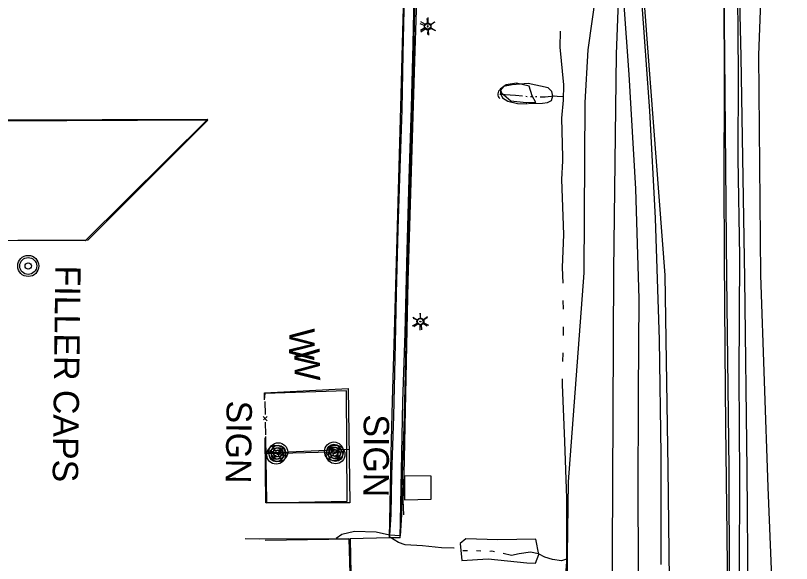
# Model space of a CAD drawing. Extents: x 588843 to 2552415, y 180129 to 269402.
# Drawn here: x 593696.8 to 593880.6, y 185185.1 to 185314.8 of the extents above; entities that cross this region are included whole.
import ezdxf

# ---------------------------------------------------------------- set-up
doc = ezdxf.new("R2010")
doc.units = 0
for name, color, linetype in [('Default', 7, 'Continuous'), ('E_BLD', 7, 'Continuous'), ('E_BLD_HvyDash', 7, 'Continuous'), ('E_DRN', 7, 'Continuous'), ('E_DRN_RipRap', 7, 'Continuous'), ('E_DWY', 7, 'Continuous'), ('E_FEN_P', 7, 'Continuous'), ('E_LTG', 7, 'Continuous'), ('E_MISCPROP', 7, 'Continuous'), ('E_MISCPROP_Text', 7, 'Continuous'), ('E_RDWY', 7, 'Continuous'), ('E_RDWY_AsphConc', 7, 'Continuous'), ('E_RDWY_C_and_G', 7, 'Continuous'), ('E_RDWY_Gravel', 7, 'Continuous'), ('E_RDWY_PavtEdge', 7, 'Continuous'), ('E_SGN', 7, 'Continuous'), ('E_SGN_Text', 7, 'Continuous'), ('E_WAL', 7, 'Continuous'), ('E_WAL_Text', 7, 'Continuous'), ('E_WTR_P', 7, 'Continuous')]:
    doc.layers.add(name, color=color, linetype=linetype)

# ---------------------------------------------------------------- blocks, each defined once
blk = doc.blocks.new('FILO')
at = {"layer": 'E_MISCPROP'}
for radius in [5, 4, 1.5]:
    blk.add_circle((0, 0), radius, dxfattribs=at)
blk = doc.blocks.new('FILT')
at = {"layer": 'E_MISCPROP_Text'}
blk.add_text('FILLER CAPS', height=12, dxfattribs=at).set_placement((12, -4))
blk = doc.blocks.new('POLE')
at = {"layer": 'Default'}
for radius in [4.46, 3.35, 2.23, 1.12]:
    blk.add_circle((0, 0), radius, dxfattribs=at)
blk = doc.blocks.new('SIGN')
at = {"layer": 'Default'}
blk.add_text('SIGN', height=12, dxfattribs=at).set_placement((-18.55, -6))
blk = doc.blocks.new('LPOL')
at = {"layer": 'Default'}
for p, q in [((-4, 0), (-1.5, 0)), ((-0.75, 1.3), (-2, 3.46)), ((0.75, 1.3), (2, 3.46)), ((1.5, 0), (4, 0)), ((-2, -3.46), (-0.75, -1.3)), ((2, -3.46), (0.75, -1.3))]:
    blk.add_line(p, q, dxfattribs=at)
for radius in [1.5, 1.5, 1.5, 0.125]:
    blk.add_circle((0, 0), radius, dxfattribs=at)
blk = doc.blocks.new('W_61')
at = {"layer": 'E_WAL_Text'}
blk.add_text('W', height=12, dxfattribs=at).set_placement((-4.46, -6))
blk = doc.blocks.new('CULV2_4')
at = {"layer": 'E_DRN'}
blk.add_arc((65, 48), 80.7, 216.8699, 323.1301, dxfattribs=at)
blk = doc.blocks.new('POLE_3')
at = {"layer": 'E_MISCPROP'}
for radius in [14.6, 11, 7.32, 3.66]:
    blk.add_circle((0, 0), radius, dxfattribs=at)
blk = doc.blocks.new('LPOL_4')
at = {"layer": 'E_LTG'}
for p, q in [((-13.1, 0), (-4.9, 0)), ((-2.5, 4.3), (-6.6, 11.4)), ((2.5, 4.3), (6.6, 11.4)), ((4.9, 0), (13.1, 0)), ((-6.6, -11.4), (-2.5, -4.3)), ((6.6, -11.4), (2.5, -4.3))]:
    blk.add_line(p, q, dxfattribs=at)
for radius in [4.92, 4.92, 4.92, 0.41]:
    blk.add_circle((0, 0), radius, dxfattribs=at)
blk = doc.blocks.new('SIGN_3')
at = {"layer": 'E_SGN'}
blk.add_text('SIGN', height=39.37, dxfattribs=at).set_placement((-56.1, -19.7))
blk = doc.blocks.new('W_8_1')
at = {"layer": 'E_WAL_Text'}
blk.add_text('W', height=39.4, dxfattribs=at).set_placement((-14.6, -19.7))

msp = doc.modelspace()

# ---------------------------------------------------------------- linework, layer by layer
at = {"layer": 'E_BLD'}
msp.add_lwpolyline([(593595.41, 185342.82), (593542.04, 185289.64), (593742.37, 185290.28), (593713.31, 185261.53), (593514.99, 185261.87), (593447.83, 185195.35), (593433.78, 185195.34), (593433.67, 185288.83), (593458.13, 185312.89)], dxfattribs=at)
at = {"layer": 'E_BLD_HvyDash'}
msp.add_lwpolyline([(593513.7, 185260.82), (593714.03, 185261.73), (593742.37, 185290.1), (593542.12, 185289.15)], dxfattribs=at)
at = {"layer": 'E_DRN_RipRap'}
for points in [[(593818.43, 185298.09), (593815.41, 185298.81), (593812.98, 185298.45), (593811.59, 185297.38), (593811.88, 185296.54), (593814.07, 185294.67), (593817.72, 185294.22), (593819.99, 185294.22), (593819.17, 185295.85)], [(593820.03, 185190.89), (593810.98, 185190.77), (593803.43, 185190.94), (593802.1, 185189.91), (593802.48, 185185.86), (593808.76, 185186.28), (593817.87, 185185.31), (593819.94, 185185.2), (593820.71, 185187.29)]]:
    msp.add_lwpolyline(points, close=True, dxfattribs=at)
msp.add_lwpolyline([(593818.26, 185294.01), (593821.56, 185294.11), (593822.78, 185294.26), (593823.7, 185294.75), (593824.08, 185295.87), (593823.81, 185296.87), (593822.93, 185297.69), (593818.23, 185298.77), (593814.42, 185298.47), (593812.35, 185298.05), (593811.64, 185297.19), (593811.65, 185296.37), (593812.12, 185295.37), (593813.38, 185294.59), (593815.66, 185294.02), (593817.94, 185293.91)], dxfattribs=at)
at = {"layer": 'E_DWY'}
for points in [[(593779.28, 185414.41), (593780.64, 185411.67), (593783.45, 185404.25), (593785.68, 185397.13), (593787.43, 185390.2), (593788.2, 185384.9), (593788.79, 185378.59), (593788.96, 185370.88), (593789.05, 185361.06), (593788.98, 185348.55), (593788.98, 185333.57), (593788.87, 185319.82), (593788.56, 185305.76), (593788.27, 185292.48), (593787.8, 185278.7), (593787.36, 185264.28), (593786.97, 185249.03), (593786.71, 185237.17), (593786.32, 185219.98), (593785.83, 185206.1), (593785.7, 185196.77), (593785.38, 185191.85)], [(593781.51, 185415.53), (593782.94, 185412.67), (593785.82, 185405.07), (593788.08, 185397.81), (593789.89, 185390.69), (593790.68, 185385.2), (593791.29, 185378.74), (593791.46, 185370.92), (593791.55, 185361.07), (593791.48, 185348.55), (593791.48, 185333.56), (593791.37, 185319.78), (593791.06, 185305.7), (593790.76, 185292.41), (593790.29, 185278.61), (593789.86, 185264.21), (593789.47, 185248.97), (593789.21, 185237.11), (593788.82, 185219.91), (593788.33, 185206.04), (593788.2, 185196.68), (593787.88, 185191.69)], [(593785.39, 185191.25), (593785.75, 185211.18), (593786.05, 185223.58), (593786.54, 185239.7), (593787.08, 185259.3), (593787.56, 185276.23), (593788.06, 185293.13), (593788.48, 185308.13), (593788.74, 185319.7), (593788.87, 185345.72)], [(593787.89, 185191.21), (593788.25, 185211.13), (593788.55, 185223.52), (593789.04, 185239.63), (593789.58, 185259.23), (593790.06, 185276.16), (593790.56, 185293.06), (593790.98, 185308.07), (593791.24, 185319.67), (593791.37, 185345.7)], [(593787.88, 185191.69), (593785.38, 185191.85), (593782.22, 185192.52), (593777.11, 185192.74), (593774.09, 185191.99), (593772.73, 185191.04)], [(593787.89, 185191.21), (593785.39, 185191.25), (593776.03, 185190.97)]]:
    msp.add_lwpolyline(points, dxfattribs=at)
at = {"layer": 'E_FEN_P'}
for p, q in [((593755.48, 185219.96), (593756.43, 185218.94)), ((593756.4, 185219.94), (593755.53, 185219.12))]:
    msp.add_line(p, q, dxfattribs=at)
for points in [[(593755.81, 185223.45), (593755.89, 185220.44)], [(593755.95, 185218.57), (593756.03, 185215.56)]]:
    msp.add_lwpolyline(points, dxfattribs=at)
at = {"layer": 'E_RDWY'}
for points in [[(593875.84, 185453.5), (593875.18, 185444.55), (593873.42, 185426.77), (593871.63, 185407.61), (593869.74, 185387.1), (593868.31, 185371.28), (593866.46, 185352.19), (593864.94, 185332.65), (593864.52, 185319.97), (593864.65, 185298.49), (593864.53, 185275.87), (593864.59, 185257.56), (593864.77, 185235.68), (593864.91, 185217.64), (593865.21, 185192.03), (593865.51, 185169.15)], [(593849.72, 185184.93), (593849.66, 185210.92), (593849.31, 185238.05), (593848.37, 185266.91), (593847.03, 185292.29), (593845.07, 185319.69), (593843.62, 185339.55), (593841.62, 185365.79), (593839.25, 185395.75), (593838.48, 185404.83), (593836.91, 185426.06)]]:
    msp.add_lwpolyline(points, dxfattribs=at)
at = {"layer": 'E_RDWY_AsphConc'}
for points in [[(593880.44, 185453.26), (593877.09, 185432.82), (593874.68, 185401.65), (593869.68, 185351.53), (593868.04, 185328.52), (593868.59, 185305.06), (593869.44, 185252.63), (593869.98, 185207.15), (593870.24, 185177.47), (593870.68, 185147.16), (593871.02, 185130.16)], [(593835.51, 185420.49), (593834.36, 185418.93), (593835.27, 185400.95), (593838.25, 185354.97), (593839.96, 185330.69), (593839.05, 185305.69), (593838.39, 185254.46), (593838.17, 185204.09), (593837.95, 185155.65), (593837.92, 185121.35)]]:
    msp.add_lwpolyline(points, dxfattribs=at)
msp.add_lwpolyline([(593788.95, 185200.24), (593795.22, 185200.33), (593795.26, 185205.82), (593788.92, 185205.9)], close=True, dxfattribs=at)
at = {"layer": 'E_RDWY_C_and_G'}
msp.add_lwpolyline([(593788.78, 185196.64), (593788.64, 185200.13), (593788.81, 185206.13), (593789.8, 185251.96), (593791.36, 185304.06), (593791.76, 185316.22), (593792.01, 185352.33), (593791.93, 185366.51), (593791.98, 185372.66), (593791.74, 185378.81), (593791.74, 185378.81), (593791.28, 185384.15), (593790.58, 185389.46), (593790.58, 185389.46)], dxfattribs=at)
at = {"layer": 'E_RDWY_Gravel'}
for points in [[(593868.28, 185183.24), (593868.29, 185205.46), (593868.14, 185229.51), (593868.36, 185257.81), (593867.92, 185280.99), (593867.98, 185300.88), (593867.76, 185329.05), (593870.2, 185354), (593873.03, 185383.38), (593875.37, 185421.39), (593876.83, 185433.85), (593880.22, 185453.87)], [(593880.55, 185453.99), (593880.27, 185436.18), (593879.73, 185413.27), (593873.51, 185372.17), (593873.98, 185339.4), (593872.71, 185305.48), (593873.23, 185253.41), (593874.93, 185203.22), (593876.95, 185154.58), (593875.43, 185130.24)], [(593844.4, 185173.99), (593844.28, 185200.35), (593844.34, 185225.47), (593844.46, 185247.8), (593843.7, 185273.84), (593842.1, 185300.87), (593840.28, 185326.16), (593838.73, 185332.58), (593837.75, 185357.97), (593836.54, 185384.48), (593835.33, 185404.73), (593834.59, 185417.58), (593834.58, 185426.2)], [(593835.27, 185400.95), (593834.53, 185396.47), (593834.76, 185386.56), (593835.08, 185373.51), (593835.55, 185355.16), (593836.58, 185329.7), (593834.99, 185325.81), (593832.31, 185306.73), (593831.63, 185294.22), (593831.36, 185253.97), (593827.7, 185204.47), (593827.4, 185187.18), (593827.61, 185159.5), (593827.62, 185153.75), (593830.2, 185149.6), (593826.76, 185143.39), (593825.88, 185131.68), (593828.3, 185120.29), (593826.54, 185087.76), (593828.55, 185057.9)]]:
    msp.add_lwpolyline(points, dxfattribs=at)
at = {"layer": 'E_RDWY_PavtEdge'}
for points in [[(593875.85, 185453.59), (593873.92, 185432.86), (593870.99, 185400.68), (593866.59, 185351.79), (593864.42, 185328.6), (593864.71, 185305.3), (593865.19, 185252.78), (593865.69, 185207.57), (593865.81, 185180.99), (593866.2, 185154.42), (593866.2, 185154.42), (593866.82, 185130.11), (593866.82, 185130.11)], [(593839.4, 185400.62), (593842.88, 185354.87), (593846.48, 185307.23), (593850.58, 185253.42), (593851.31, 185207.69), (593851.9, 185154.74), (593851.9, 185154.74), (593852.41, 185121.99), (593852.41, 185121.99), (593853.62, 185093.61), (593853.62, 185093.61), (593854.67, 185076.65), (593855.94, 185059.71), (593855.94, 185059.71)]]:
    msp.add_lwpolyline(points, dxfattribs=at)
at = {"layer": 'E_SGN'}
msp.add_line((593756.39, 185211.19), (593774.53, 185211.66), dxfattribs=at)
msp.add_lwpolyline([(593756.14, 185211.36), (593775.77, 185212.17)], dxfattribs=at)
at = {"layer": 'E_WAL'}
for points in [[(593755.78, 185224.17), (593755.77, 185225.51), (593775.57, 185226.58), (593775.97, 185199.5), (593756.08, 185199.52), (593755.96, 185214.88)], [(593756.04, 185215.19), (593756.27, 185199.52), (593775.34, 185199.92), (593775.21, 185226.04), (593755.86, 185225.41), (593755.72, 185223.85)], [(593751.17, 185191.06), (593754.62, 185190.99), (593775.72, 185191.05), (593776.46, 185166.13), (593756.49, 185166)], [(593755.91, 185190.69), (593776.03, 185190.97), (593776.5, 185166.35), (593756.58, 185166.17)]]:
    msp.add_lwpolyline(points, dxfattribs=at)
at = {"layer": 'E_WTR_P'}
for points in [[(593825.76, 185311.16), (593825.74, 185307.36), (593826.54, 185298.42), (593826.49, 185294.8), (593826.06, 185290.58), (593826.33, 185281.34)], [(593811.5, 185296.21), (593815.22, 185295.99), (593816.87, 185295.82)], [(593817.62, 185295.75), (593818, 185295.71)], [(593818.76, 185295.67), (593819.14, 185295.66)], [(593819.9, 185295.65), (593820.27, 185295.64)], [(593821.03, 185295.63), (593822.23, 185295.61), (593824.33, 185295.81), (593825.03, 185295.76), (593826.5, 185295.66)], [(593826.33, 185281.34), (593826.36, 185280.46), (593826.06, 185275.99), (593826.53, 185263), (593826.28, 185255.2), (593826.38, 185251.49)], [(593826.45, 185247.37), (593826.46, 185245.31)], [(593826.47, 185241.19), (593826.47, 185239.13)], [(593826.41, 185235.01), (593826.37, 185232.95)], [(593826.28, 185228.83), (593826.25, 185227.49), (593826.77, 185213.98), (593827.24, 185200.64), (593827.24, 185198.97)], [(593827.24, 185198.97), (593827.27, 185187.73), (593827.24, 185185.54), (593826.81, 185179.57), (593826.86, 185173.47), (593827.24, 185169.13)], [(593800.69, 185188.74), (593800.59, 185188.77), (593797.7, 185188.86), (593793.18, 185189.32), (593789.04, 185189.52), (593787.48, 185190.13), (593785.43, 185191.35)], [(593803.83, 185188.14), (593802.8, 185188.12), (593802.76, 185188.13)], [(593807.03, 185188.05), (593805.97, 185188.15)], [(593810.22, 185187.9), (593809.58, 185188.02), (593809.16, 185187.99)], [(593827.25, 185186.19), (593826.12, 185185.8), (593823.99, 185186.07), (593822.12, 185186.67), (593820.61, 185187.42), (593818.78, 185187.81), (593816.04, 185187.39), (593814.25, 185187.04), (593812.31, 185187.49)]]:
    msp.add_lwpolyline(points, dxfattribs=at)

# ---------------------------------------------------------------- block references
at = {"layer": 'E_DRN', "xscale": 0.017300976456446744, "yscale": 0.017300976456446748, "rotation": -93.43141079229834}
msp.add_blockref('CULV2_4', (593811.65, 185297.41), dxfattribs=at)
at = {"layer": 'E_LTG'}
for name, p, xscale, yscale, rotation in [('LPOL_4', (593794.41, 185312.15), 0.1524003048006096, 0.15240030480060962, -84.36014555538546), ('LPOL', (593794.42, 185312.38), 0.5000000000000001, 0.5, -90.72490345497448), ('LPOL', (593792.59, 185242.4), 0.5000000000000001, 0.5, -90.72490345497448), ('LPOL_4', (593792.77, 185242.41), 0.1524003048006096, 0.15240030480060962, -84.36014555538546)]:
    msp.add_blockref(name, p, dxfattribs=dict(at, xscale=xscale, yscale=yscale, rotation=rotation))
at = {"layer": 'E_MISCPROP'}
for name, p, xscale, yscale, rotation in [('FILO', (593699.82, 185255.56), 0.5000000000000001, 0.5, -90.72490345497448), ('POLE', (593759.03, 185211.48), 0.5000000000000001, 0.5, -90.72490345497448), ('POLE', (593772.22, 185211.67), 0.5000000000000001, 0.5, -90.72490345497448), ('POLE_3', (593758.54, 185210.87), 0.1524003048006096, 0.15240030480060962, -84.36014555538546), ('POLE_3', (593772.6, 185210.96), 0.1524003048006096, 0.15240030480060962, -84.36014555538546)]:
    msp.add_blockref(name, p, dxfattribs=dict(at, xscale=xscale, yscale=yscale, rotation=rotation))
at = {"layer": 'E_MISCPROP_Text', "xscale": 0.5000000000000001, "yscale": 0.5, "rotation": -90.72490345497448}
msp.add_blockref('FILT', (593708.32, 185261.66), dxfattribs=at)
at = {"layer": 'E_SGN_Text'}
for name, p, xscale, yscale, rotation in [('SIGN', (593749.69, 185214.42), 0.5000000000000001, 0.5, -90.72490345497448), ('SIGN_3', (593782.24, 185211.89), 0.1524003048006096, 0.1524003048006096, -90.18446500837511)]:
    msp.add_blockref(name, p, dxfattribs=dict(at, xscale=xscale, yscale=yscale, rotation=rotation))
at = {"layer": 'E_WAL_Text'}
for name, p, xscale, yscale, rotation in [('W_8_1', (593764.62, 185238.59), 0.1524003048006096, 0.15240030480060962, -90.23323317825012), ('W_61', (593765.86, 185233.77), 0.49999999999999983, 0.4999999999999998, -88.93139815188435)]:
    msp.add_blockref(name, p, dxfattribs=dict(at, xscale=xscale, yscale=yscale, rotation=rotation))

doc.saveas('drawing.dxf')
